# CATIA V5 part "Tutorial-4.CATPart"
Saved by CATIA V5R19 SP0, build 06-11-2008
Part number: Part1
Bounding box of the stored display mesh (mm): x -3 to 154, y -3 to 154, z -47 to 3.015
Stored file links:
  D:\Shriniwas\v5_r19\Part files\C15\TUT4.CATPart
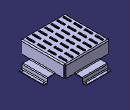
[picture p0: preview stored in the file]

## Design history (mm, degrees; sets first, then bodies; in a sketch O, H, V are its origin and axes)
SheetMetalParameters1: BendRadius 2, ReliefAxialLength 2, ReliefRadialLength 1, MinimumBendRadius 0, Thickness 1, KFactor 0.400515 {= log(min(100,max(20*SheetMetalParameters1.BendRadius,SheetMetalParameters1.Thickness)/SheetMetalParameters1.Thickness))/log(100)/2}
Body1 (main body)
  Sketch1 on xy-plane, origin (0, 0, 0), H (1, 0, 0), V (0, 1, 0)
    line L1 (0, 0) -> (120, 0)
    line L2 (120, 0) -> (120, 120)
    line L3 (120, 120) -> (0, 120)
    line L4 (0, 120) -> (0, 0)
    length L3 = 120
    length L2 = 120
    horizontal: L1 H, L3 H
    vertical: L2 V, L4 V
  Wall1: Thickness 1, Profile Sketch1
  Flange1: Length 34, Radius 2, Angle 90, KFacteur 0.400515 {= log(min(100,max(20*Flange1.Radius,SheetMetalParameters1.Thickness)/SheetMetalParameters1.Thickness))/log(100)/2}, Guide edge [face of Wall1 | face of Wall1]
  Flange2: Length 34, Radius 2, Angle 90, KFacteur 0.400515 {= log(min(100,max(20*Flange2.Radius,SheetMetalParameters1.Thickness)/SheetMetalParameters1.Thickness))/log(100)/2}, Guide edge [face of Wall1 | face of Wall1]
  Flange3: Length 34, Radius 2, Angle 90, KFacteur 0.400515 {= log(min(100,max(20*Flange3.Radius,SheetMetalParameters1.Thickness)/SheetMetalParameters1.Thickness))/log(100)/2}, Guide edge [face of Wall1 | face of Wall1]
  Flange4: Length 34, Radius 2, Angle 90, KFacteur 0.400515 {= log(min(100,max(20*Flange4.Radius,SheetMetalParameters1.Thickness)/SheetMetalParameters1.Thickness))/log(100)/2}, Guide edge [face of Wall1 | face of Wall1]
  d_NewWallOnEdge1: NewWallOnEdge_HeightLimitOffset 0, NewWallOnEdge_Length 21, NewWallOnEdge_Edge edge [face of Flange3 | face of Flange3], NewWallOnEdge_WidthOffset1 -25, NewWallOnEdge_WidthOffset2 -25, NewWallOnEdge_Angle 90, KFacteur 0.400515 {= log(min(100,max(20*d_NewWallOnEdge1.Radius,SheetMetalParameters1.Thickness)/SheetMetalParameters1.Thickness))/log(100)/2}, NewWallOnEdge_BendTable SheetMetalParameters1, NewWallOnEdge_BendRadiusValue 2 {= SheetMetalParameters1.BendRadius}
  Flange5: Length 13, Radius 1, Angle 90, KFacteur 0.325257 {= log(min(100,max(20*Flange5.Radius,SheetMetalParameters1.Thickness)/SheetMetalParameters1.Thickness))/log(100)/2}, Guide edge [face of d_NewWallOnEdge1 | face of d_NewWallOnEdge1]
  d_NewWallOnEdge2: NewWallOnEdge_HeightLimitOffset 0, NewWallOnEdge_Length 10, NewWallOnEdge_Edge edge [face of Flange5 | face of Flange5], NewWallOnEdge_WidthOffset1 0, NewWallOnEdge_WidthOffset2 0, NewWallOnEdge_Angle 90, KFacteur 0.400515 {= log(min(100,max(20*d_NewWallOnEdge2.Radius,SheetMetalParameters1.Thickness)/SheetMetalParameters1.Thickness))/log(100)/2}, NewWallOnEdge_BendTable SheetMetalParameters1, NewWallOnEdge_BendRadiusValue 2 {= SheetMetalParameters1.BendRadius}
  d_NewWallOnEdge3: NewWallOnEdge_HeightLimitOffset 0, NewWallOnEdge_Length 21, NewWallOnEdge_Edge edge [face of Flange2 | face of Flange2], NewWallOnEdge_WidthOffset1 -25, NewWallOnEdge_WidthOffset2 -25, NewWallOnEdge_Angle 90, KFacteur 0.400515 {= log(min(100,max(20*d_NewWallOnEdge3.Radius,SheetMetalParameters1.Thickness)/SheetMetalParameters1.Thickness))/log(100)/2}, NewWallOnEdge_BendTable SheetMetalParameters1, NewWallOnEdge_BendRadiusValue 2 {= SheetMetalParameters1.BendRadius}
  Flange6: Length 13, Radius 1, Angle 90, KFacteur 0.325257 {= log(min(100,max(20*Flange6.Radius,SheetMetalParameters1.Thickness)/SheetMetalParameters1.Thickness))/log(100)/2}, Guide edge [face of d_NewWallOnEdge3 | face of d_NewWallOnEdge3]
  d_NewWallOnEdge4: NewWallOnEdge_HeightLimitOffset 0, NewWallOnEdge_Length 10, NewWallOnEdge_Edge edge [face of Flange6 | face of Flange6], NewWallOnEdge_WidthOffset1 0, NewWallOnEdge_WidthOffset2 0, NewWallOnEdge_Angle 90, KFacteur 0.400515 {= log(min(100,max(20*d_NewWallOnEdge4.Radius,SheetMetalParameters1.Thickness)/SheetMetalParameters1.Thickness))/log(100)/2}, NewWallOnEdge_BendTable SheetMetalParameters1, NewWallOnEdge_BendRadiusValue 2 {= SheetMetalParameters1.BendRadius}
  Sketch2 on face of d_NewWallOnEdge2, origin (31.3691, 147.6369, -46), H (1, 0, 0), V (0, 1, 0)
    point P1 (-1.3691, 2.3631)
    reference projected line E1 (-6.3691, 6.3631) -> (63.6309, 6.3631) from edge [face of d_NewWallOnEdge2 | face of d_NewWallOnEdge2]
    reference projected line E2 (-6.3691, -0.6369) -> (-6.3691, 6.3631) from edge [face of d_NewWallOnEdge2 | face of d_NewWallOnEdge2]
    distance P1 E1 = 4
    distance P1 E2 = 5
  Hole1: placed by Sketch2, at (30, 150, -46) direction (0, 0, -1), diameter 3, through (limit type 6)
  Sketch3 on face of d_NewWallOnEdge2, origin (79.2942, 150.7856, -46), H (1, 0, 0), V (0, 1, 0)
    point P1 (10.7058, -0.7856)
    reference projected line E1 (-54.2942, 3.2144) -> (15.7058, 3.2144) from edge [face of d_NewWallOnEdge2 | face of d_NewWallOnEdge2]
    reference projected line E2 (15.7058, 3.2144) -> (15.7058, -3.7856) from edge [face of d_NewWallOnEdge2 | face of d_NewWallOnEdge2]
    distance P1 E1 = 4
    distance P1 E2 = 5
  Hole2: placed by Sketch3, at (90, 150, -46) direction (0, 0, -1), diameter 3, through (limit type 6)
  Sketch4 on face of d_NewWallOnEdge4, origin (148.0642, 84.3582, -46), H (1, 0, 0), V (0, 1, 0)
    point P1 (1.9358, 5.6418)
    reference projected line E1 (5.9358, 10.6418) -> (5.9358, -59.3582) from edge [face of d_NewWallOnEdge4 | face of d_NewWallOnEdge4]
    reference projected line E2 (-1.0642, 10.6418) -> (5.9358, 10.6418) from edge [face of d_NewWallOnEdge4 | face of d_NewWallOnEdge4]
    distance P1 E1 = 4
    distance P1 E2 = 5
  Hole3: placed by Sketch4, at (150, 90, -46) direction (0, 0, -1), diameter 3, through (limit type 6)
  Sketch5 on face of d_NewWallOnEdge4, origin (149.1042, 61.7681, -46), H (1, 0, 0), V (0, 1, 0)
    point P1 (0.8958, -31.7681)
    reference projected line E1 (4.8958, -36.7681) -> (-2.1042, -36.7681) from edge [face of d_NewWallOnEdge4 | face of d_NewWallOnEdge4]
    reference projected line E2 (4.8958, 33.2319) -> (4.8958, -36.7681) from edge [face of d_NewWallOnEdge4 | face of d_NewWallOnEdge4]
    distance E1 P1 = 5
    distance P1 E2 = 4
  Hole4: placed by Sketch5, at (150, 30, -46) direction (0, 0, -1), diameter 3, through (limit type 6)
  Sketch6 on face of Wall1, origin (0, 0, 0), H (1, 0, 0), V (0, -1, 0)
    line L1 (112, -115) -> (109.5, -115)
    line L2 (109.5, -115) -> (109.5, -95)
    line L3 (109.5, -95) -> (112, -95)
    line L4 (112, -95) -> (112, -115)
    reference projected line E1 (0, -123) -> (120, -123) from edge [face of Flange3 | face of Flange3]
    reference projected line E2 (123, -120) -> (123, 0) from edge [face of Flange2 | face of Flange2]
    distance L2 L4 = 2.5
    length L2 = 20
    distance L1 E1 = 8
    distance L4 E2 = 11
    horizontal: L1 H, L3 H
    vertical: L2 V, L4 V
  d_Stamp1: Stamp_FilletRadius 0.25, NewRoot_AttribNormalisation "No Standard"
  RectPattern1: of d_Stamp1, direction 1 instances 7, spacing 17, along edge [face of Flange3 | face of Flange3] reversed, direction 2 instances 4, spacing 30, along edge [face of Flange2 | face of Flange2]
